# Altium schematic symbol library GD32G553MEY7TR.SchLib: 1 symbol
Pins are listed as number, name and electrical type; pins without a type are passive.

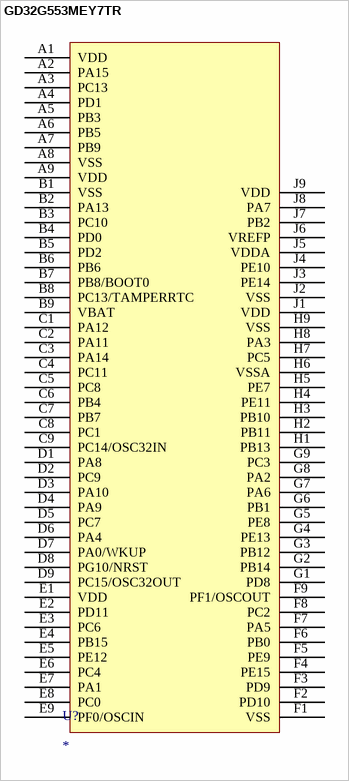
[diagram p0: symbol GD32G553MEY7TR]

## GD32G553MEY7TR
designator U?
footprint GD32G553MEY7TR
pins: A1 VDD, A2 PA15, A3 PC13, A4 PD1, A5 PB3, A6 PB5, A7 PB9, A8 VSS, A9 VDD, B1 VSS, B2 PA13, B3 PC10, B4 PD0, B5 PD2, B6 PB6, B7 PB8/BOOT0, B8 PC13/TAMPERRTC, B9 VBAT, C1 PA12, C2 PA11, C3 PA14, C4 PC11, C5 PC8, C6 PB4, C7 PB7, C8 PC1, C9 PC14/OSC32IN, D1 PA8, D2 PC9, D3 PA10, D4 PA9, D5 PC7, D6 PA4, D7 PA0/WKUP, D8 PG10/NRST, D9 PC15/OSC32OUT, E1 VDD, E2 PD11, E3 PC6, E4 PB15, E5 PE12, E6 PC4, E7 PA1, E8 PC0, E9 PF0/OSCIN, F1 VSS, F2 PD10, F3 PD9, F4 PE15, F5 PE9, F6 PB0, F7 PA5, F8 PC2, F9 PF1/OSCOUT, G1 PD8, G2 PB14, G3 PB12, G4 PE13, G5 PE8, G6 PB1, G7 PA6, G8 PA2, G9 PC3, H1 PB13, H2 PB11, H3 PB10, H4 PE11, H5 PE7, H6 VSSA, H7 PC5, H8 PA3, H9 VSS, J1 VDD, J2 VSS, J3 PE14, J4 PE10, J5 VDDA, J6 VREFP, J7 PB2, J8 PA7, J9 VDD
